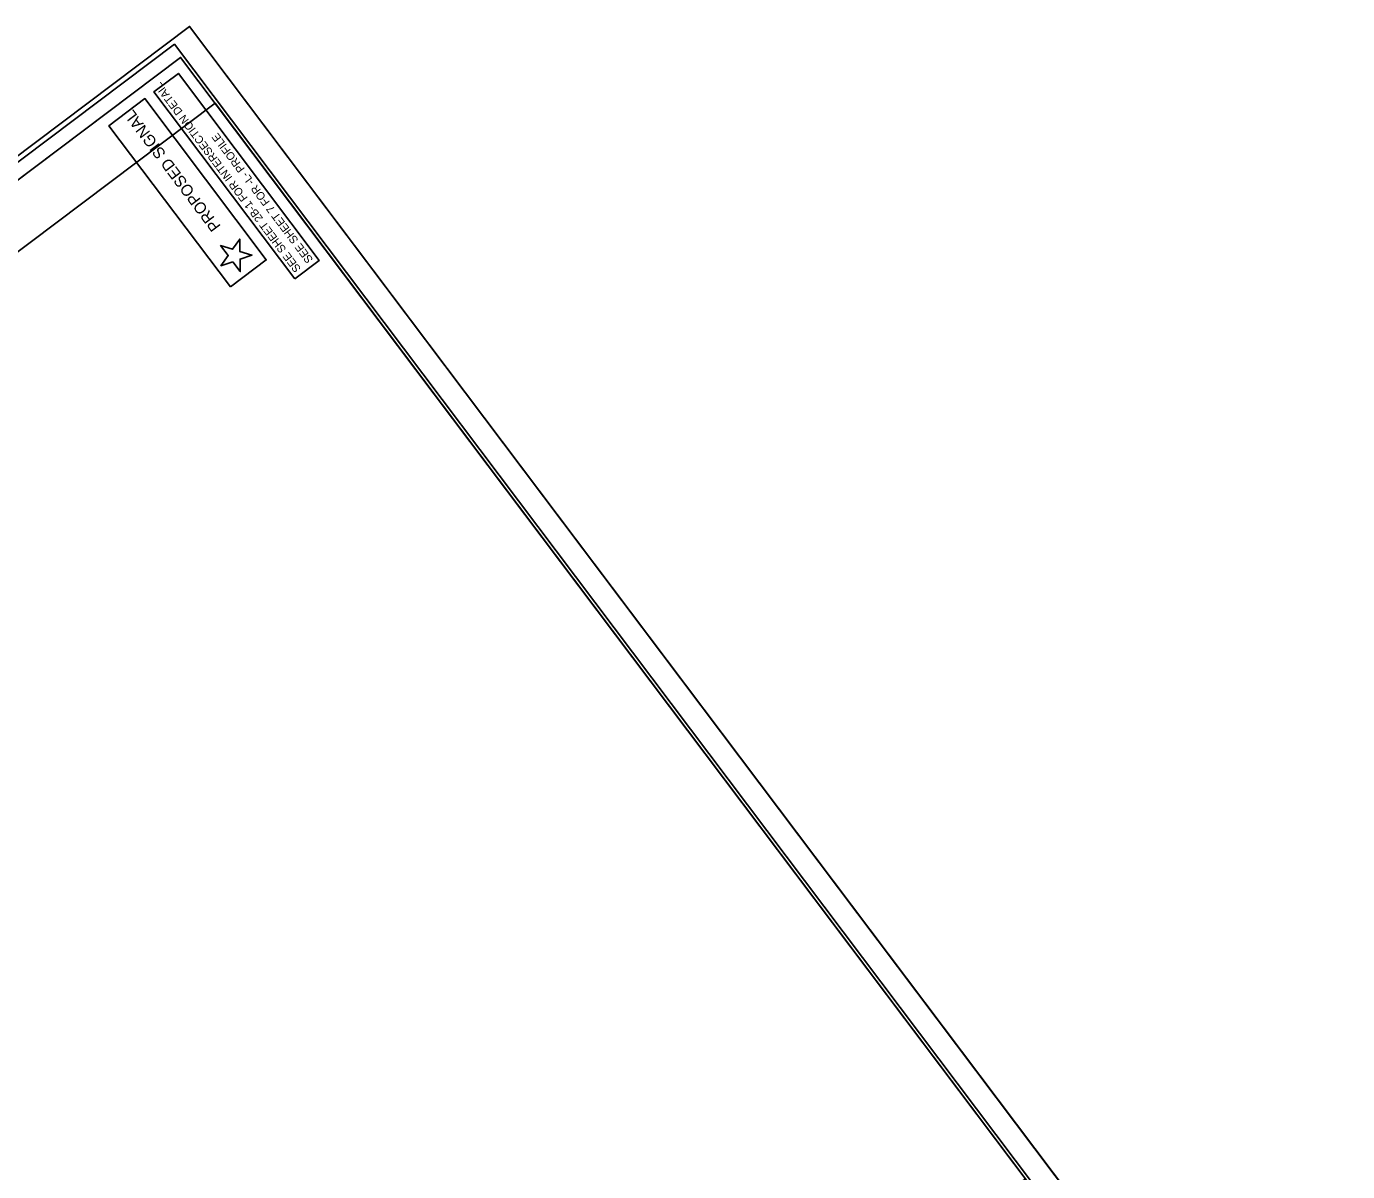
# Model space of a CAD drawing. Extents: x 1261689 to 1263694, y 776294 to 778298.
# Drawn here: x 1262538 to 1263694, y 777296 to 778298 of the extents above; entities that cross this region are included whole.
import ezdxf

# ---------------------------------------------------------------- set-up
doc = ezdxf.new("R2010")
doc.units = 0
for name, color, linetype in [('Prop DSN Text', 7, 'Continuous'), ('Prop Grid Mask', 7, 'Continuous'), ('Prop PHM Label Text', 7, 'Continuous'), ('Prop RDY Traffic Signal CELL', 7, 'Continuous'), ('Sheet Clip Boundary CELL', 7, 'Continuous'), ('Sheet Cutting Line CELL', 7, 'Continuous'), ('Sheet Layout Plan Border', 7, 'Continuous'), ('Sheet Plan CELL', 7, 'Continuous'), ('Sheet Plan Layout CELL', 7, 'Continuous'), ('Sheet Plot Border Inside CELL', 7, 'Continuous'), ('Sheet Plot Border Outside CELL', 7, 'Continuous')]:
    doc.layers.add(name, color=color, linetype=linetype)

msp = doc.modelspace()

# ---------------------------------------------------------------- linework, layer by layer
at = {"layer": 'Prop Grid Mask'}
msp.add_lwpolyline([(1262716.7, 778069.6), (1262610.5, 778210.6), (1262641.9, 778234.3), (1262748.1, 778093.2)], close=True, dxfattribs=at)
at = {"layer": 'Prop PHM Label Text'}
msp.add_lwpolyline([(1262773, 778076.7), (1262649.9, 778240.3), (1262671.2, 778256.4), (1262794.4, 778092.8)], close=True, dxfattribs=at)
at = {"layer": 'Prop RDY Traffic Signal CELL'}
msp.add_lwpolyline([(1262718.9, 778091.7), (1262725.4, 778083), (1262725.2, 778093.9), (1262735.5, 778097.4), (1262725.1, 778100.6), (1262724.9, 778111.5), (1262718.7, 778102.6), (1262708.2, 778105.8), (1262714.8, 778097.1), (1262708.5, 778088.1), (1262718.9, 778091.7)], dxfattribs=at)
at = {"layer": 'Sheet Clip Boundary CELL'}
msp.add_lwpolyline([(1263412, 777289.5), (1262673.2, 778270.4), (1262003.4, 777765.9), (1262147.4, 777574.8), (1261978.4, 777447.5), (1262573.3, 776657.8)], close=True, dxfattribs=at)
at = {"layer": 'Sheet Cutting Line CELL'}
msp.add_line((1263693.8, 776952.8), (1262681, 778297.5), dxfattribs=at)
at = {"layer": 'Sheet Layout Plan Border'}
msp.add_lwpolyline([(1263545.6, 777112.2), (1262703.3, 778230.4), (1262033.5, 777726), (1262147.4, 777574.8), (1261978.4, 777447.5), (1262706.9, 776480.4)], close=True, dxfattribs=at)
at = {"layer": 'Sheet Plan CELL'}
msp.add_lwpolyline([(1261834.5, 777638.7), (1262737, 776440.5), (1263575.7, 777072.2), (1262673.2, 778270.4)], close=True, dxfattribs=at)
at = {"layer": 'Sheet Plan Layout CELL'}
msp.add_lwpolyline([(1262737, 776440.5), (1263575.7, 777072.2), (1262673.2, 778270.4), (1262003.4, 777765.9), (1262147.4, 777574.8), (1261978.4, 777447.5)], close=True, dxfattribs=at)
at = {"layer": 'Sheet Plot Border Inside CELL'}
msp.add_lwpolyline([(1263670, 776951.1), (1262667.7, 778281.9), (1261825, 777647.1), (1262827.3, 776316.4)], close=True, dxfattribs=at)
at = {"layer": 'Sheet Plot Border Outside CELL'}
msp.add_lwpolyline([(1263693.8, 776952.8), (1262681, 778297.5), (1261806.3, 777638.7), (1262819.2, 776294)], close=True, dxfattribs=at)

# ---------------------------------------------------------------- texts
at = {"layer": 'Prop DSN Text'}
msp.add_text('PROPOSED SIGNAL', height=10, rotation=126.9874, dxfattribs=at).set_placement((1262708.7, 778122.8))
at = {"layer": 'Prop PHM Label Text'}
for s, p in [('SEE SHEET 2B-1 FOR INTERSECTION DETAIL', (1262778.8, 778085.6)), ('SEE SHEET 7 FOR -L- PROFILE', (1262789.4, 778093.6))]:
    msp.add_text(s, height=7, rotation=126.9874, dxfattribs=at).set_placement(p)

doc.saveas('drawing.dxf')
